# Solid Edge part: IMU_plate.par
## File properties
Author: wojci
Template: ISO Metric Part.par
Last saved by: wojci
Revision: 12
Application: Solid Edge
Username: wojci
Accuracy: 0.990
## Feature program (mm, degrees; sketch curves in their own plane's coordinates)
sketch used by "ExtrudedProtrusion_1" plane through (0, 0, 0) normal (0, 0, 1) x-axis (1, 0, 0)
  line (-29, 5) -> (18, 5)
  line (18, 5) -> (18, -5)
  line (18, -5) -> (-29, -5)
  line (-29, -5) -> (-29, 5)
  line (18, 5) -> (18, 70)
  line (18, 70) -> (-29, 70)
  line (-29, 70) -> (-29, 5)
  dimension (linear) = 18
  dimension (linear) = 29
  dimension (linear) = 18
extrude "ExtrudedProtrusion_1" add finite 3 along +normal
sketch for "unnamed Protrusion 1" #1 plane through (-2, 14, 3) normal (0, 0, 1) x-axis (1, 0, 0)
  circle centre (3, -4) radius 3
sketch for "unnamed Protrusion 1" #2 plane through (-2, 14, 3) normal (0, 0, 1) x-axis (1, 0, 0)
  circle centre (3, 14) radius 3
sketch for "unnamed Protrusion 1" #3 plane through (-2, 14, 3) normal (0, 0, 1) x-axis (1, 0, 0)
  line (-5, 14) -> (-5, -4)
  line (-5, -4) -> (-3, -4)
  line (-3, -4) -> (-3, 14)
  line (-3, 14) -> (-5, 14)
extrude "unnamed Protrusion 1" add finite 3.5 along +normal
sketch for "ExtrudedProtrusion_3" plane through (-2, 14, 3) normal (0, 0, 1) x-axis (1, 0, 0)
  line (4, 14) -> (4, -4)
  line (4, -4) -> (2, -4)
  line (2, -4) -> (2, 14)
  line (2, 14) -> (4, 14)
extrude "ExtrudedProtrusion_3" add finite 3 along +normal
sketch for "unnamed Cutout 1" plane through (-5, 7, 4.75) normal (1, 0, 0) x-axis (0, 1, 0)
  line (8, 1.75) -> (10.0207, -1.75)
  line (13.9793, -1.75) -> (10.0207, -1.75)
  line (16, 1.75) -> (13.9793, -1.75)
  line (8, 1.75) -> (16, 1.75)
extrude "unnamed Cutout 1" cut through along -normal
sketch for "Hole_1" plane through (-2, 14, 3) normal (0, 0, 1) x-axis (1, 0, 0)
  hole centre (-15, -14) bore radius 1.7
hole "Hole_1" diameter 3.4 through
sketch for "unnamed Hole 1" plane through (-2, 14, 3) normal (0, 0, 1) x-axis (1, 0, 0)
  hole centre (15, -14) bore radius 1.7
hole "unnamed Hole 1" through
pattern "unnamed Pattern 1" of "Hole_1", "unnamed Hole 1"
sketch for "unnamed Hole 2" plane through (-5.5, 32.5, 3) normal (0, 0, 1) x-axis (0, 1, 0)
  hole centre (11.5, -1.5) bore radius 1.7
hole "unnamed Hole 2" through
sketch for "Hole_3" plane through (1, -2, 6.5) normal (0, 0, 1) x-axis (0, 1, 0)
  hole centre (12, 0) bore radius 1.0065
hole "Hole_3" nominal diameter 2.5 through  ThreadDepth = 2 mm
sketch for "unnamed Hole 3" plane through (1, -2, 6.5) normal (0, 0, 1) x-axis (0, 1, 0)
  hole centre (30, 0) bore radius 1.0065
hole "unnamed Hole 3" through
pattern "unnamed Pattern 2" of "Hole_3", "unnamed Hole 3"
sketch for "ExtrudedProtrusion_7" #1 plane through (-5.5, 32.5, 3) normal (0, 0, 1) x-axis (0, 1, 0)
  circle centre (-24, -19.5) radius 3
sketch for "ExtrudedProtrusion_7" #2 plane through (-5.5, 32.5, 3) normal (0, 0, 1) x-axis (0, 1, 0)
  circle centre (32, -19.5) radius 3
sketch for "ExtrudedProtrusion_7" #3 plane through (-5.5, 32.5, 3) normal (0, 0, 1) x-axis (0, 1, 0)
  circle centre (32, -0.5) radius 3
extrude "ExtrudedProtrusion_7" add finite 9.5 along +normal
sketch for "ExtrudedProtrusion_8" #1 plane through (-5.5, 32.5, 3) normal (0, 0, 1) x-axis (0, 1, 0)
  line (32, -20.5) -> (-24, -20.5)
  line (-24, -20.5) -> (-24, -18.5)
  line (-24, -18.5) -> (32, -18.5)
  line (32, -18.5) -> (32, -20.5)
sketch for "ExtrudedProtrusion_8" #2 plane through (-5.5, 32.5, 3) normal (0, 0, 1) x-axis (0, 1, 0)
  line (33, -0.5) -> (33, -19.5)
  line (33, -19.5) -> (31, -19.5)
  line (31, -19.5) -> (31, -0.5)
  line (31, -0.5) -> (33, -0.5)
extrude "ExtrudedProtrusion_8" add finite 7 along +normal
sketch for "unnamed Cutout 2" plane through (4.5, 65.5, 5) normal (0, 1, 0) x-axis (-1, 0, 0)
  line (-4.6716, 5) -> (-3.0639, -1)
  line (-3.0639, -1) -> (3.0639, -1)
  line (4.6716, 5) -> (3.0639, -1)
  line (-4.6716, 5) -> (4.6716, 5)
extrude "unnamed Cutout 2" cut through along -normal
sketch for "unnamed Cutout 3" #1 plane through (14, 8.5, 12.5) normal (0, 0, 1) x-axis (0, 1, 0)
  line (53, 3) -> (59, 3)
  line (59, 3) -> (59, 2.2)
  line (59, 2.2) -> (53, 2.2)
  line (53, 2.2) -> (53, 3)
sketch for "unnamed Cutout 3" #2 plane through (14, 8.5, 12.5) normal (0, 0, 1) x-axis (0, 1, 0)
  line (53.5, 16.8) -> (59, 16.8)
  line (59, 16.8) -> (59, 16)
  line (59, 16) -> (53, 16)
  line (53, 16) -> (53, 22)
  line (53, 22) -> (53.5, 22)
  line (53.5, 22) -> (53.5, 16.8)
extrude "unnamed Cutout 3" cut to key point along -normal
sketch for "Hole_8" plane through (14, 8.5, 12.5) normal (0, 0, 1) x-axis (0, 1, 0)
  hole centre (0, 0) bore radius 1.0065
hole "Hole_8" nominal diameter 2.5 through  ThreadDepth = 2 mm
sketch for "unnamed Hole 4" plane through (14, 8.5, 12.5) normal (0, 0, 1) x-axis (0, 1, 0)
  hole centre (56, 0) bore radius 1.0065
hole "unnamed Hole 4" through
sketch for "unnamed Hole 5" plane through (14, 8.5, 12.5) normal (0, 0, 1) x-axis (0, 1, 0)
  hole centre (56, 19) bore radius 1.0065
hole "unnamed Hole 5" through
pattern "unnamed Pattern 3" of "Hole_8", "unnamed Hole 4", "unnamed Hole 5"
sketch for "ExtrudedProtrusion_9" plane through (-5.5, 32.5, 3) normal (0, 0, 1) x-axis (0, 1, 0)
  line (37.5, 23.5) -> (48, 23.5)
  line (48, 23.5) -> (48, 1.0406)
  line (48, 1.0406) -> (37.5, 1.0406)
  line (37.5, 1.0406) -> (37.5, 23.5)
extrude "ExtrudedProtrusion_9" add finite 3 along -normal
sketch for "ExtrudedProtrusion_10" plane through (-5.5, 32.5, 3) normal (0, 0, 1) x-axis (0, 1, 0)
  circle centre (43, 7.5) radius 4
extrude "ExtrudedProtrusion_10" add finite 9 along +normal
sketch for "ExtrudedCutout_5" plane through (-5.5, 32.5, 3) normal (0, 0, 1) x-axis (0, 1, 0)
  line (43, 13.5) -> (3, 13.5)
  line (3, 13.5) -> (3, 16.5)
  line (3, 16.5) -> (43, 16.5)
  line (43, 16.5) -> (43, 13.5)
extrude "ExtrudedCutout_5" cut finite 1 along -normal
sketch for "ExtrudedProtrusion_11" #1 plane through (-5.5, 32.5, 3) normal (0, 0, 1) x-axis (0, 1, 0)
  line (35, 12.5) -> (5.9994, 12.5)
  line (5.9994, 12.5) -> (5.9994, 10.5)
  line (5.9994, 10.5) -> (35, 10.5)
  line (35, 10.5) -> (35, 12.5)
sketch for "ExtrudedProtrusion_11" #2 plane through (-5.5, 32.5, 3) normal (0, 0, 1) x-axis (0, 1, 0)
  line (5.9994, 8.5) -> (35, 8.5)
  line (35, 8.5) -> (35, 6.5)
  line (35, 6.5) -> (5.9994, 6.5)
  line (5.9994, 6.5) -> (5.9994, 8.5)
extrude "ExtrudedProtrusion_11" add finite 4 along +normal
chamfer "Chamfer_3" setback 2
sketch for "Hole_11" plane through (-13, 75.5, 12) normal (0, 0, 1) x-axis (-1, 0, 0)
hole "Hole_11" diameter 3 through  ThreadDepth = 2 mm
chamfer "Chamfer_4" setback 10.5
sketch for "unnamed Cutout 4" plane through (-5.5, 37.75, 3) normal (0, 0, 1) x-axis (0, 1, 0)
extrude "unnamed Cutout 4" cut through along -normal
chamfer "Chamfer_5" setback 7
fillet "Round_3" radius 6
fillet "Round_4" radius 5
chamfer "Chamfer_6" setback 1
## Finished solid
Body 1: solid body, 91 faces, 215 edges, 124 vertices.
  Faces by surface: plane 62, cylinder 29
  Edges by curve: line 152, circle 63
Bounding box of the edges (mm): 47.000 x 85.500 x 12.500, from (-29, -5, 0) to (18, 80.5, 12.5).
Cylindrical faces by radius (mm): R1.0065 x10, R1.2295 x2, R1.7 x3, R3 x5, R4 x1, R5 x4, R6 x4
Planar faces by outward normal: +x 9, +y 6, +z 18, -x 10, -y 6, -z 1, oblique 12
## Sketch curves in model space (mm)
circle centre (14, 64.5, 3) radius 3
circle centre (-5, 64.5, 3) radius 3
circle centre (14, 8.5, 3) radius 3
line (-29, 64.5, 3) -> (18, 64.5, 3)
line (-29, 8.5, 3) -> (18, 8.5, 3)
line (14, -5, 3) -> (14, 70, 3)
line (-5, 65.5, 3) -> (14, 65.5, 3)
line (14, 65.5, 3) -> (14, 63.5, 3)
line (14, 63.5, 3) -> (-5, 63.5, 3)
line (-5, 63.5, 3) -> (-5, 65.5, 3)
line (13, 64.5, 3) -> (15, 64.5, 3)
line (15, 64.5, 3) -> (15, 8.5, 3)
line (15, 8.5, 3) -> (13, 8.5, 3)
line (13, 8.5, 3) -> (13, 64.5, 3)
line (-5, -5, 3) -> (-5, 70, 3)
circle centre (-13, 75.5, 3) radius 4
line (-29, 75.5, 3) -> (-6.5406, 75.5, 3)
line (-14, -5, 3) -> (-14, 70, 3)
line (-16, -5, 3) -> (-16, 70, 3)
line (-22, -5, 3) -> (-22, 70, 3)
line (-22, 75.5, 3) -> (-19, 75.5, 3)
line (-19, 75.5, 3) -> (-19, 35.5, 3)
line (-19, 35.5, 3) -> (-22, 35.5, 3)
line (-22, 35.5, 3) -> (-22, 75.5, 3)
line (-14, 67.5, 3) -> (-12, 67.5, 3)
line (-12, 67.5, 3) -> (-12, 38.4994, 3)
line (-12, 38.4994, 3) -> (-14, 38.4994, 3)
line (-14, 38.4994, 3) -> (-14, 67.5, 3)
line (-16, 67.5, 3) -> (-18, 67.5, 3)
line (-18, 67.5, 3) -> (-18, 38.4994, 3)
line (-18, 38.4994, 3) -> (-16, 38.4994, 3)
line (-16, 38.4994, 3) -> (-16, 67.5, 3)
line (-29, 80.5, 3) -> (-6.5406, 80.5, 3)
line (-6.5406, 80.5, 3) -> (-6.5406, 70, 3)
line (-6.5406, 70, 3) -> (-29, 70, 3)
line (-29, 70, 3) -> (-29, 80.5, 3)
circle centre (1, 28, 3) radius 3
circle centre (1, 10, 3) radius 3
line (3.5, 5.5, 3) -> (-12, 5.5, 3)
line (-12, 32.5, 3) -> (3.5, 32.5, 3)
line (-29, 28, 3) -> (18, 28, 3)
line (-6, 70, 3) -> (-6, -5, 3)
line (-5, 10, 3) -> (-5, 28, 3)
line (-5, 28, 3) -> (-7, 28, 3)
line (-7, 28, 3) -> (-7, 10, 3)
line (-7, 10, 3) -> (-5, 10, 3)
line (2, 28, 3) -> (2, 10, 3)
line (2, 10, 3) -> (0, 10, 3)
line (0, 10, 3) -> (0, 28, 3)
line (0, 28, 3) -> (2, 28, 3)
line (-12, 5.5, 3) -> (-12, 32.5, 3)
line (3.5, 32.5, 3) -> (3.5, 5.5, 3)
line (1, 70, 3) -> (1, -5, 3)
line (0, -5, 3) -> (0, 70, 3)
line (-29, 5, 0) -> (18, 5, 0)
line (-29, 5, 0) -> (18, 5, 0)
line (13, 5, 0) -> (13, -5, 0)
line (-17, 5, 0) -> (-17, -5, 0)
line (0, 7.5, 0) -> (0, -5, 0)
line (-29, -5, 0) -> (-29, 5, 0)
line (18, -5, 0) -> (-29, -5, 0)
line (18, 5, 0) -> (18, -5, 0)
line (-29, 70, 0) -> (-29, 5, 0)
line (18, 70, 0) -> (-29, 70, 0)
line (18, 5, 0) -> (18, 70, 0)
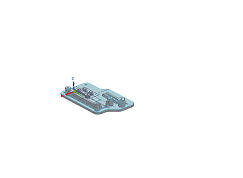
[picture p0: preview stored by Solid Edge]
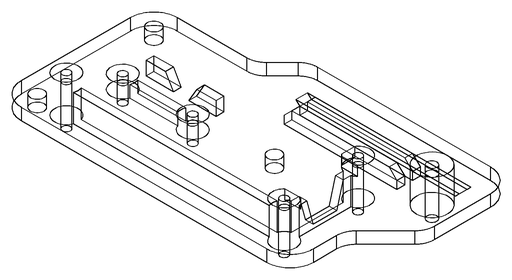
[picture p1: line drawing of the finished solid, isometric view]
